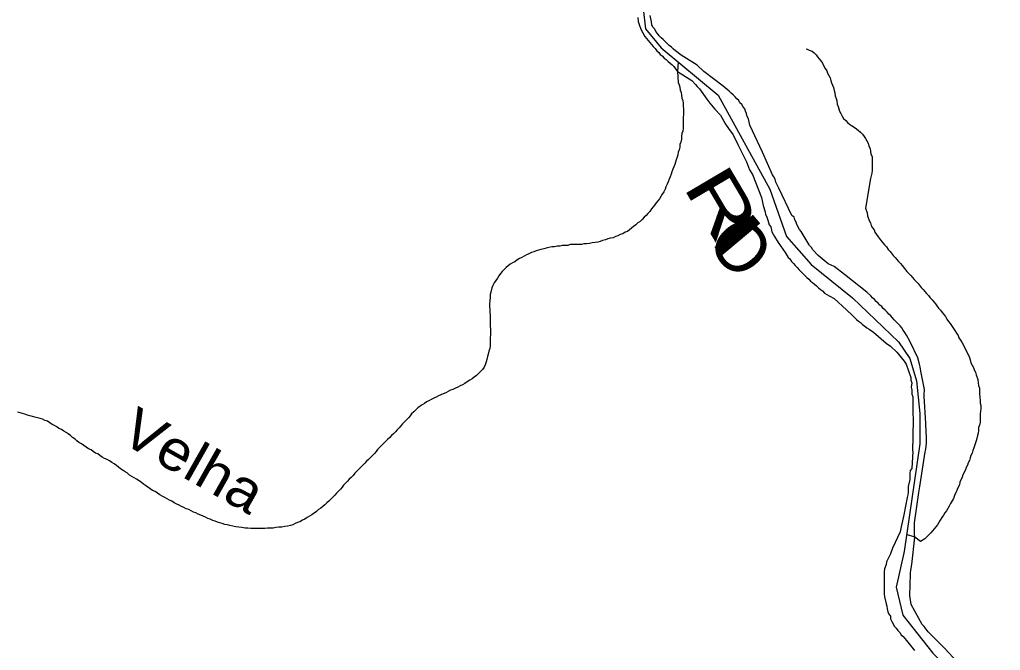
# Model space of a CAD drawing. Extents: x 652.3 to 678, y 7316.9 to 7344.9.
# Drawn here: x 655.117 to 657.066, y 7339.464 to 7340.717 of the extents above; entities that cross this region are included whole.
import ezdxf
from ezdxf.enums import TextEntityAlignment as Align

# ---------------------------------------------------------------- set-up
doc = ezdxf.new("R2010")
doc.units = 0
doc.header["$LTSCALE"] = 0.032
for name, color, linetype, lineweight in [('2', 7, 'Continuous', 25), ('55', 7, 'Continuous', 25), ('7', 7, 'Continuous', 25)]:
    doc.layers.add(name, color=color, linetype=linetype, lineweight=lineweight)
doc.layers.add('61', color=7, linetype='Continuous')

msp = doc.modelspace()

# ---------------------------------------------------------------- linework, layer by layer
at = {"layer": '2'}
for points in [[(656.3454, 7340.7216), (656.3462, 7340.7137), (656.3478, 7340.7081), (656.351, 7340.6985), (656.3589, 7340.6842), (656.3661, 7340.6763), (656.3693, 7340.6723), (656.3724, 7340.6683), (656.3756, 7340.6643), (656.3796, 7340.6603), (656.3828, 7340.6556), (656.3868, 7340.6524), (656.3899, 7340.6484), (656.3939, 7340.6452), (656.3979, 7340.6412), (656.4019, 7340.6381), (656.4059, 7340.6341), (656.4098, 7340.6309), (656.4138, 7340.6277), (656.417, 7340.6245), (656.4242, 7340.6142)], [(656.6613, 7340.3102), (656.6597, 7340.315), (656.6573, 7340.3198), (656.6557, 7340.3246), (656.6517, 7340.3285), (656.6255, 7340.3826), (656.6199, 7340.3946), (656.6183, 7340.4002), (656.6159, 7340.4049), (656.6127, 7340.4089), (656.5928, 7340.4543), (656.5682, 7340.5076), (656.565, 7340.5203), (656.5626, 7340.5251), (656.561, 7340.5306), (656.5594, 7340.5354), (656.5578, 7340.5402), (656.5547, 7340.5442), (656.5523, 7340.5489), (656.5483, 7340.5521), (656.5459, 7340.5569), (656.5419, 7340.5601), (656.5387, 7340.5641), (656.5348, 7340.568), (656.5308, 7340.5712), (656.5268, 7340.5752), (656.5228, 7340.5784), (656.5149, 7340.5855), (656.4767, 7340.6142), (656.4632, 7340.6269), (656.4313, 7340.6468), (656.4202, 7340.6556), (656.4162, 7340.6588), (656.4122, 7340.6627), (656.4075, 7340.6659), (656.4035, 7340.6699), (656.3995, 7340.6739), (656.3955, 7340.6778), (656.3915, 7340.681), (656.3876, 7340.685), (656.3844, 7340.6898), (656.3812, 7340.6938), (656.3788, 7340.6985), (656.3748, 7340.7025), (656.3732, 7340.7073), (656.3724, 7340.7129), (656.3701, 7340.7256)], [(656.4242, 7340.6142), (656.4242, 7340.6142), (656.4528, 7340.5967)], [(656.4528, 7340.5967), (656.46, 7340.5887), (656.4632, 7340.5848), (656.4671, 7340.5808), (656.4679, 7340.58), (656.4822, 7340.5593), (656.4886, 7340.5513), (656.4918, 7340.5474), (656.495, 7340.5434), (656.4982, 7340.5394), (656.5093, 7340.5275), (656.5196, 7340.51), (656.5252, 7340.5012), (656.5348, 7340.4885), (656.5443, 7340.4694), (656.5483, 7340.4614), (656.561, 7340.4352), (656.5674, 7340.4192), (656.573, 7340.4097), (656.5913, 7340.3643), (656.5928, 7340.354), (656.5944, 7340.3484), (656.5984, 7340.3357), (656.5992, 7340.3301), (656.6016, 7340.3254), (656.6048, 7340.3142), (656.6064, 7340.3094), (656.6096, 7340.3055), (656.6119, 7340.2959), (656.6143, 7340.2911), (656.6167, 7340.2864), (656.6239, 7340.2744), (656.6382, 7340.2545), (656.6438, 7340.245), (656.6477, 7340.2418), (656.6509, 7340.237), (656.6549, 7340.2331), (656.6581, 7340.2291), (656.6621, 7340.2251), (656.6653, 7340.2211), (656.6692, 7340.2171), (656.6732, 7340.2132), (656.6772, 7340.2092), (656.6812, 7340.2052), (656.6851, 7340.202), (656.6883, 7340.198), (656.6923, 7340.1949), (656.6963, 7340.1917), (656.7003, 7340.1885), (656.7042, 7340.1845), (656.7082, 7340.1813), (656.7122, 7340.1782), (656.7162, 7340.1742), (656.721, 7340.171), (656.7257, 7340.1686), (656.7353, 7340.163), (656.7599, 7340.1408), (656.7719, 7340.1296), (656.7759, 7340.1256), (656.7798, 7340.1217), (656.7838, 7340.1185), (656.7878, 7340.1153), (656.7918, 7340.1113), (656.7965, 7340.1081), (656.8005, 7340.105), (656.8053, 7340.1026), (656.814, 7340.0962), (656.8387, 7340.0747), (656.8475, 7340.0683), (656.8602, 7340.0564), (656.8745, 7340.0389)], [(656.67, 7340.2967), (656.6668, 7340.3007), (656.6613, 7340.3102)], [(656.6859, 7340.2697), (656.67, 7340.2967), (656.67, 7340.2967)], [(656.756, 7340.2108), (656.7353, 7340.2267), (656.7233, 7340.2323), (656.7194, 7340.2354), (656.7154, 7340.2386), (656.7034, 7340.249), (656.6931, 7340.2601), (656.6907, 7340.2649), (656.6867, 7340.2689), (656.6859, 7340.2697)], [(656.9803, 7339.4413), (656.9557, 7339.4676), (656.9501, 7339.4732), (656.9223, 7339.501), (656.9143, 7339.5114), (656.9103, 7339.5153), (656.8888, 7339.5551), (656.8857, 7339.5734), (656.8873, 7339.6156), (656.8873, 7339.618), (656.888, 7339.6236), (656.8896, 7339.6347), (656.896, 7339.6888), (656.8952, 7339.6952), (656.8952, 7339.7007), (656.8952, 7339.7063), (656.8952, 7339.7175), (656.904, 7339.7779), (656.9056, 7339.7899), (656.9167, 7339.8583), (656.9175, 7339.8639), (656.9191, 7339.8758), (656.9191, 7339.8885), (656.9183, 7339.8981), (656.9175, 7339.9148), (656.9143, 7339.9689), (656.9143, 7339.9721), (656.9151, 7339.9824), (656.9079, 7340.019), (656.9063, 7340.0278), (656.9048, 7340.0325), (656.9016, 7340.0453), (656.8865, 7340.0771), (656.8793, 7340.0906), (656.8761, 7340.0954), (656.8729, 7340.1002), (656.8697, 7340.105), (656.8666, 7340.1089), (656.8626, 7340.1129), (656.8586, 7340.1169), (656.8546, 7340.1209), (656.8514, 7340.1248), (656.8483, 7340.1288), (656.8443, 7340.132), (656.8411, 7340.136), (656.8371, 7340.14), (656.8331, 7340.1431), (656.83, 7340.1471), (656.826, 7340.1503), (656.8228, 7340.1543), (656.8188, 7340.1575), (656.8156, 7340.1614), (656.8117, 7340.1646), (656.8085, 7340.1686), (656.8005, 7340.1758), (656.756, 7340.2108)], [(656.8745, 7340.0389), (656.8785, 7340.0325), (656.888, 7340.0063), (656.888, 7340.0007), (656.8896, 7339.9959), (656.8888, 7339.9872), (656.8896, 7339.9816), (656.8896, 7339.9729), (656.892, 7339.9681), (656.892, 7339.9625), (656.892, 7339.9347), (656.8928, 7339.9243), (656.892, 7339.8893), (656.8912, 7339.8607), (656.892, 7339.8591), (656.8896, 7339.8257), (656.8865, 7339.8217), (656.8857, 7339.8161), (656.8857, 7339.8034), (656.8825, 7339.7899), (656.8825, 7339.7843), (656.8825, 7339.7787), (656.8817, 7339.7731), (656.8809, 7339.7676), (656.8737, 7339.7334), (656.869, 7339.7095), (656.8666, 7339.6999), (656.8514, 7339.6673), (656.8475, 7339.6562), (656.8395, 7339.6403), (656.8387, 7339.6347), (656.8355, 7339.6259), (656.8347, 7339.6204), (656.8347, 7339.6148), (656.8347, 7339.6092), (656.8347, 7339.6037), (656.8347, 7339.5981), (656.8347, 7339.5925), (656.8347, 7339.587), (656.8347, 7339.5814), (656.8347, 7339.5758), (656.8355, 7339.5702), (656.8387, 7339.5567), (656.8403, 7339.5519), (656.8411, 7339.5464), (656.8419, 7339.5408), (656.8443, 7339.536), (656.8475, 7339.5321), (656.8475, 7339.5265), (656.8499, 7339.5217), (656.853, 7339.5169), (656.8546, 7339.5122), (656.8586, 7339.5082), (656.8618, 7339.5034), (656.8658, 7339.4994), (656.869, 7339.4947), (656.8729, 7339.4915), (656.8793, 7339.4835), (656.8952, 7339.4636)]]:
    msp.add_lwpolyline(points, dxfattribs=at)
at = {"layer": '55'}
for p, q in [((656.4252, 7340.6333), (656.4242, 7340.6142)), ((656.896, 7339.6888), (656.8794, 7339.6942))]:
    msp.add_line(p, q, dxfattribs=at)
for points in [[(656.3558, 7340.7392), (656.3603, 7340.6991), (656.3914, 7340.6612), (656.505, 7340.5676), (656.6074, 7340.3804), (656.6408, 7340.2868), (656.6898, 7340.2311), (656.7721, 7340.1643), (656.8634, 7340.0774), (656.8857, 7340.044), (656.899, 7339.9994), (656.9057, 7339.9348), (656.9057, 7339.8747), (656.8746, 7339.6608), (656.859, 7339.5895)], [(656.859, 7339.5895), (656.8723, 7339.5339), (656.9315, 7339.4588), (657.0607, 7339.3274), (657.2098, 7339.1848), (657.2967, 7339.0846), (657.31, 7339.0189), (657.29, 7338.9743), (657.1386, 7338.8852), (657.0206, 7338.8518), (656.8781, 7338.834), (656.7668, 7338.814), (656.7222, 7338.8117), (656.6888, 7338.8362), (656.6644, 7338.8852), (656.6555, 7338.9142), (656.6501, 7338.9361)]]:
    msp.add_lwpolyline(points, dxfattribs=at)
at = {"layer": '7'}
for points in [[(656.6798, 7340.6595), (656.6801, 7340.6593), (656.6816, 7340.6587), (656.6831, 7340.6581), (656.6846, 7340.6575), (656.6861, 7340.657), (656.6875, 7340.6564), (656.6915, 7340.6548), (656.6955, 7340.6516), (656.6995, 7340.6476), (656.7027, 7340.6436), (656.7058, 7340.6397), (656.709, 7340.6357), (656.7122, 7340.6309), (656.7146, 7340.6261), (656.7178, 7340.6206), (656.721, 7340.6158), (656.7225, 7340.611), (656.7249, 7340.6062), (656.7273, 7340.6015), (656.7289, 7340.5967), (656.7305, 7340.5919), (656.7321, 7340.5871), (656.7345, 7340.5824), (656.7353, 7340.5768), (656.7369, 7340.572), (656.7377, 7340.5657), (656.7393, 7340.5609), (656.7408, 7340.5561), (656.7416, 7340.5497), (656.7432, 7340.545), (656.7448, 7340.5402), (656.7464, 7340.5354), (656.7488, 7340.5306), (656.7512, 7340.5259), (656.7544, 7340.5211), (656.7584, 7340.5171), (656.7623, 7340.5131), (656.7663, 7340.51), (656.7703, 7340.5068), (656.7751, 7340.5036), (656.7798, 7340.5004), (656.7838, 7340.4972), (656.7878, 7340.494), (656.7918, 7340.4901), (656.795, 7340.4853), (656.7981, 7340.4813), (656.8005, 7340.4765), (656.8029, 7340.4718), (656.8045, 7340.4662), (656.8069, 7340.4614), (656.8077, 7340.4558), (656.8085, 7340.4503), (656.8109, 7340.4455), (656.8109, 7340.4399), (656.8109, 7340.4344), (656.8109, 7340.4288), (656.8109, 7340.4232), (656.8109, 7340.4177), (656.8101, 7340.4121), (656.8077, 7340.4017), (656.7981, 7340.3429), (656.8013, 7340.3333), (656.8021, 7340.3277), (656.8053, 7340.3182), (656.8077, 7340.3134), (656.8093, 7340.3086), (656.8117, 7340.3039), (656.8148, 7340.2999), (656.8164, 7340.2951), (656.8196, 7340.2903), (656.8228, 7340.2856), (656.8292, 7340.2776), (656.8323, 7340.2736), (656.8355, 7340.2697)], [(656.4242, 7340.6142), (656.4242, 7340.6142), (656.4242, 7340.6142), (656.4242, 7340.6142), (656.4258, 7340.5927)], [(656.4289, 7340.5832), (656.4297, 7340.5776), (656.4313, 7340.5728), (656.4321, 7340.5672), (656.4329, 7340.5617), (656.4345, 7340.5569), (656.4353, 7340.5513), (656.4353, 7340.5458), (656.4361, 7340.5402), (656.4361, 7340.5346), (656.4361, 7340.5291), (656.4353, 7340.5235), (656.4353, 7340.5179), (656.4353, 7340.5123), (656.4353, 7340.5068), (656.4353, 7340.5012), (656.4345, 7340.4956), (656.4329, 7340.4909), (656.4321, 7340.4853), (656.4321, 7340.4797), (656.4305, 7340.4742), (656.4289, 7340.4694), (656.4289, 7340.4638), (656.4273, 7340.459), (656.4258, 7340.4543), (656.425, 7340.4487), (656.4234, 7340.4439), (656.4218, 7340.4391), (656.4202, 7340.4344), (656.4186, 7340.4296), (656.417, 7340.4248), (656.4146, 7340.42), (656.413, 7340.4153), (656.4114, 7340.4105), (656.4098, 7340.4049), (656.4075, 7340.4002), (656.4059, 7340.3954), (656.4035, 7340.3906), (656.4011, 7340.385), (656.3995, 7340.3803), (656.3971, 7340.3755), (656.3939, 7340.3707), (656.3907, 7340.3659), (656.3884, 7340.3612), (656.3852, 7340.3572), (656.382, 7340.3532), (656.3788, 7340.3492), (656.3756, 7340.3452), (656.3724, 7340.3413), (656.3693, 7340.3365), (656.3653, 7340.3325), (656.3621, 7340.3285), (656.3581, 7340.3246), (656.3541, 7340.3206), (656.3502, 7340.3166), (656.3454, 7340.3134), (656.3414, 7340.3094), (656.3366, 7340.3063), (656.3327, 7340.3031), (656.3287, 7340.2999), (656.3247, 7340.2967), (656.3199, 7340.2951), (656.3152, 7340.2919), (656.3104, 7340.2903), (656.3056, 7340.288), (656.3008, 7340.2864), (656.2961, 7340.284), (656.2905, 7340.2832), (656.2857, 7340.2816), (656.2809, 7340.28), (656.2754, 7340.2784), (656.2706, 7340.2768), (656.2658, 7340.2752), (656.2602, 7340.2744), (656.2547, 7340.2736), (656.2491, 7340.2728), (656.2435, 7340.272), (656.238, 7340.272), (656.2332, 7340.2705), (656.2276, 7340.2705), (656.2221, 7340.2705), (656.2165, 7340.2705), (656.2109, 7340.2705), (656.2061, 7340.2689), (656.2006, 7340.2689), (656.195, 7340.2689), (656.1902, 7340.2673), (656.1847, 7340.2673), (656.1799, 7340.2657), (656.1743, 7340.2657), (656.1687, 7340.2649), (656.1632, 7340.2633), (656.1584, 7340.2617), (656.1528, 7340.2609), (656.1481, 7340.2593), (656.1433, 7340.2577), (656.1385, 7340.2561), (656.1337, 7340.2545), (656.129, 7340.2522), (656.1242, 7340.2498), (656.1194, 7340.2474)], [(656.4258, 7340.5927), (656.4273, 7340.5879), (656.4289, 7340.5832)], [(656.8355, 7340.2697), (656.8395, 7340.2657), (656.8427, 7340.2609), (656.8467, 7340.2569), (656.853, 7340.249), (656.857, 7340.245), (656.8634, 7340.237), (656.8674, 7340.2331), (656.8705, 7340.2291), (656.8801, 7340.2171), (656.888, 7340.2092), (656.8944, 7340.2012), (656.8984, 7340.1973), (656.9024, 7340.1933), (656.9087, 7340.1853), (656.9127, 7340.1813), (656.9191, 7340.1734), (656.9231, 7340.1694), (656.9262, 7340.1646), (656.9302, 7340.1606), (656.9334, 7340.1567), (656.9366, 7340.1527), (656.9398, 7340.1487), (656.943, 7340.1439), (656.9469, 7340.14), (656.9501, 7340.1352), (656.9533, 7340.1312), (656.9565, 7340.1272), (656.9597, 7340.1225), (656.9628, 7340.1177), (656.966, 7340.1137), (656.9756, 7340.0994), (656.9788, 7340.0946), (656.9819, 7340.0898), (656.9835, 7340.0851), (656.9867, 7340.0803), (656.9899, 7340.0755), (656.9971, 7340.0612), (656.9994, 7340.0564), (657.0026, 7340.0508), (657.0042, 7340.0461), (657.0058, 7340.0413), (657.0074, 7340.0357), (657.0098, 7340.031), (657.0122, 7340.0262), (657.0138, 7340.0214), (657.0162, 7340.0166), (657.0177, 7340.0119), (657.0209, 7340.0023), (657.0217, 7339.9959), (657.0225, 7339.9904), (657.0241, 7339.9848), (657.0241, 7339.9737), (657.0257, 7339.9609), (657.0257, 7339.9554), (657.0273, 7339.9506), (657.0273, 7339.945), (657.0265, 7339.9394), (657.0257, 7339.9339), (657.0257, 7339.9172), (657.0241, 7339.9116), (657.0225, 7339.9068), (657.0225, 7339.9013), (657.0217, 7339.8957), (657.0201, 7339.8909), (657.0193, 7339.8853), (657.0177, 7339.8806), (657.013, 7339.8662), (657.0114, 7339.8615), (657.0098, 7339.8559), (657.0074, 7339.8511), (657.0058, 7339.8464), (657.0042, 7339.8416), (657.0018, 7339.8368), (657.0002, 7339.832), (656.9979, 7339.8273), (656.9963, 7339.8225), (656.9915, 7339.8129), (656.9899, 7339.8082), (656.9851, 7339.7986), (656.9843, 7339.793), (656.9819, 7339.7883), (656.9803, 7339.7835), (656.978, 7339.7787), (656.9756, 7339.7739), (656.9724, 7339.766), (656.9668, 7339.7556), (656.9644, 7339.7509), (656.9613, 7339.7461), (656.9589, 7339.7413), (656.9557, 7339.7373), (656.9525, 7339.7326), (656.9493, 7339.7278), (656.9461, 7339.723), (656.9437, 7339.7182), (656.9406, 7339.7135), (656.9278, 7339.6976), (656.9199, 7339.6896), (656.9159, 7339.6856), (656.9071, 7339.6801), (656.896, 7339.6888)], [(656.1194, 7340.2474), (656.1146, 7340.245), (656.1099, 7340.2426), (656.1051, 7340.2394), (656.1011, 7340.2362), (656.0963, 7340.2339), (656.0916, 7340.2315), (656.0876, 7340.2283), (656.0836, 7340.2251), (656.0796, 7340.2211), (656.0756, 7340.2171), (656.0725, 7340.2132), (656.0693, 7340.2084), (656.0661, 7340.2036), (656.0629, 7340.1988), (656.0597, 7340.1941), (656.0573, 7340.1893), (656.055, 7340.1845), (656.0534, 7340.1758), (656.0518, 7340.171), (656.0518, 7340.1654), (656.051, 7340.1591), (656.0502, 7340.1527), (656.0502, 7340.1471), (656.051, 7340.1416), (656.051, 7340.136), (656.0518, 7340.1304), (656.0518, 7340.1248), (656.0518, 7340.1193), (656.0518, 7340.1137), (656.0518, 7340.1081), (656.0526, 7340.1026), (656.0526, 7340.097), (656.0526, 7340.0914), (656.0518, 7340.0859), (656.0518, 7340.0803), (656.0518, 7340.0747), (656.0518, 7340.0691), (656.051, 7340.0636), (656.0494, 7340.0588), (656.0478, 7340.0524), (656.0462, 7340.0477), (656.0454, 7340.0421), (656.0438, 7340.0373), (656.0422, 7340.0317), (656.0398, 7340.027), (656.0367, 7340.0222), (656.0327, 7340.0182), (656.0287, 7340.0142), (656.0247, 7340.0103), (656.02, 7340.0071), (656.016, 7340.0039), (656.0112, 7340.0007), (656.0064, 7339.9975), (656.0017, 7339.9944), (655.9969, 7339.992), (655.9921, 7339.9896), (655.9873, 7339.9872), (655.9826, 7339.9848), (655.9778, 7339.9824), (655.973, 7339.9808), (655.9682, 7339.9784), (655.9635, 7339.976), (655.9587, 7339.9737), (655.9539, 7339.9721), (655.9491, 7339.9697), (655.9444, 7339.9673), (655.9396, 7339.9649), (655.9348, 7339.9625), (655.93, 7339.9601), (655.9253, 7339.9577), (655.9213, 7339.9546), (655.9165, 7339.9522), (655.9125, 7339.949), (655.9078, 7339.9458), (655.9038, 7339.9418), (655.8998, 7339.9379), (655.8958, 7339.9339), (655.8926, 7339.9299), (655.8895, 7339.9259), (655.8855, 7339.9219), (655.8815, 7339.918), (655.8775, 7339.914), (655.8743, 7339.91), (655.8712, 7339.906), (655.8672, 7339.9021), (655.864, 7339.8981), (655.86, 7339.8941), (655.856, 7339.8909), (655.8521, 7339.8869), (655.8481, 7339.883), (655.8441, 7339.879), (655.8401, 7339.875), (655.8361, 7339.871), (655.8322, 7339.867), (655.8282, 7339.8631), (655.825, 7339.8591), (655.8218, 7339.8551), (655.8178, 7339.8511), (655.8139, 7339.8471), (655.8099, 7339.8432)], [(655.3396, 7339.8098), (655.3349, 7339.8121), (655.3309, 7339.8161), (655.3261, 7339.8185), (655.3221, 7339.8217), (655.3174, 7339.8249), (655.3134, 7339.8281), (655.3094, 7339.8312), (655.3046, 7339.8344), (655.2999, 7339.8376), (655.2951, 7339.8408), (655.2903, 7339.8432), (655.2855, 7339.8456), (655.2808, 7339.8479), (655.276, 7339.8511), (655.272, 7339.8543), (655.2672, 7339.8559), (655.2625, 7339.8591), (655.2585, 7339.8623), (655.2537, 7339.8647), (655.2489, 7339.8678), (655.2442, 7339.871), (655.2394, 7339.8742), (655.2346, 7339.8774), (655.2306, 7339.8806), (655.2267, 7339.8837), (655.2219, 7339.8869), (655.2179, 7339.8909), (655.2131, 7339.8941), (655.2091, 7339.8973), (655.2044, 7339.8997), (655.1996, 7339.9028), (655.1948, 7339.9052), (655.1908, 7339.9084), (655.1861, 7339.9108), (655.1813, 7339.9132), (655.1765, 7339.9164), (655.1717, 7339.9196), (655.167, 7339.9211), (655.1622, 7339.9235), (655.1574, 7339.9251), (655.1519, 7339.9259), (655.1471, 7339.9275), (655.1423, 7339.9291), (655.1367, 7339.9299), (655.132, 7339.9315), (655.1272, 7339.9331), (655.1224, 7339.9347), (655.1176, 7339.9363), (655.1121, 7339.9371)], [(655.8099, 7339.8432), (655.8059, 7339.84), (655.8027, 7339.836), (655.7988, 7339.832), (655.7948, 7339.8281), (655.7908, 7339.8241), (655.7868, 7339.8201), (655.7828, 7339.8161), (655.7797, 7339.8113), (655.7757, 7339.8074), (655.7717, 7339.8042), (655.7685, 7339.8002), (655.7645, 7339.7962), (655.7606, 7339.7922), (655.7574, 7339.7883), (655.7542, 7339.7843), (655.7502, 7339.7803), (655.7462, 7339.7763), (655.7431, 7339.7724), (655.7391, 7339.7684), (655.7351, 7339.7644), (655.7311, 7339.7604), (655.7271, 7339.7572), (655.7232, 7339.7533), (655.7192, 7339.7501), (655.7152, 7339.7469), (655.7104, 7339.7437), (655.7065, 7339.7397), (655.7017, 7339.7365), (655.6977, 7339.7334), (655.6929, 7339.731), (655.6881, 7339.7278), (655.6834, 7339.7246), (655.6786, 7339.723), (655.6738, 7339.7198), (655.6691, 7339.7182), (655.6643, 7339.7159), (655.6595, 7339.7135), (655.6547, 7339.7119), (655.6492, 7339.7111), (655.6436, 7339.7103), (655.638, 7339.7087), (655.6317, 7339.7087), (655.6261, 7339.7079), (655.6205, 7339.7071), (655.6149, 7339.7071), (655.6094, 7339.7071), (655.6038, 7339.7063), (655.5982, 7339.7063), (655.5927, 7339.7063), (655.5871, 7339.7063), (655.5815, 7339.7063), (655.576, 7339.7063), (655.5704, 7339.7071), (655.5648, 7339.7071), (655.5585, 7339.7079), (655.5521, 7339.7087), (655.5465, 7339.7095), (655.5402, 7339.7111), (655.5346, 7339.7119), (655.5298, 7339.7135), (655.5242, 7339.7143), (655.5195, 7339.7159), (655.5147, 7339.7175), (655.5099, 7339.719), (655.5051, 7339.7206), (655.5004, 7339.7222), (655.4956, 7339.7246), (655.4908, 7339.7262), (655.486, 7339.7286), (655.4813, 7339.731), (655.4765, 7339.7326), (655.4717, 7339.735), (655.4669, 7339.7373), (655.4622, 7339.7389), (655.4574, 7339.7413), (655.4526, 7339.7437), (655.4479, 7339.7453), (655.4431, 7339.7477), (655.4383, 7339.7501), (655.4335, 7339.7525), (655.4288, 7339.7548), (655.424, 7339.7572), (655.4192, 7339.7604), (655.4144, 7339.7628), (655.4097, 7339.7652), (655.4049, 7339.7676), (655.4001, 7339.7708), (655.3953, 7339.7731), (655.3906, 7339.7763), (655.3858, 7339.7795), (655.381, 7339.7819), (655.3762, 7339.7851), (655.3715, 7339.7883), (655.3667, 7339.7914), (655.3627, 7339.7946), (655.3587, 7339.7978), (655.354, 7339.801), (655.3492, 7339.8042), (655.3444, 7339.8066), (655.3396, 7339.8098)]]:
    msp.add_lwpolyline(points, dxfattribs=at)

# ---------------------------------------------------------------- texts
at = {"layer": '61'}
for s, height, rotation, width, p in [('R', 0.1, 300.585, 1.45, (656.4692, 7340.3265)), ('I', 0.1, 309.989, 1.8, (656.5048, 7340.2569)), ('Velha', 0.08, 330.499, 1.1, (655.4429, 7339.8067))]:
    msp.add_text(s, height=height, rotation=rotation, dxfattribs=dict(at, width=width)).set_placement(p, align=Align.CENTER)
msp.add_text('O', height=0.1, rotation=310.963, dxfattribs=at).set_placement((656.5125, 7340.2336), align=Align.CENTER)

doc.saveas('drawing.dxf')
